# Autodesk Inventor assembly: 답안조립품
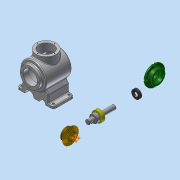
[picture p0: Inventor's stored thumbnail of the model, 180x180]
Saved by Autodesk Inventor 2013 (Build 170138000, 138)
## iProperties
Created: 2018-08
Part Number: 답안조립품
Document SubType Name: Assembly
Designer: dgall
Author: dgall
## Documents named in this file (9)
- C:\Users\dgall\Desktop\480807V1015\답안조립품.iam
- C:\Users\dgall\Desktop\480807V1015\본체.ipt
- C:\Users\dgall\Desktop\480807V1015\메인 베벨기어.ipt
- C:\Users\dgall\Desktop\480807V1015\메인 축.ipt
- 메인 축.ipt
- C:\Users\dgall\Desktop\480807V1015\베어링 6203.ipt
- C:\Users\dgall\Desktop\480807V1015\오일실 17 32 8.ipt
- C:\Users\dgall\Desktop\480807V1015\커버.ipt
- C:\Users\dgall\Desktop\480807V1015\키 5x5.ipt
